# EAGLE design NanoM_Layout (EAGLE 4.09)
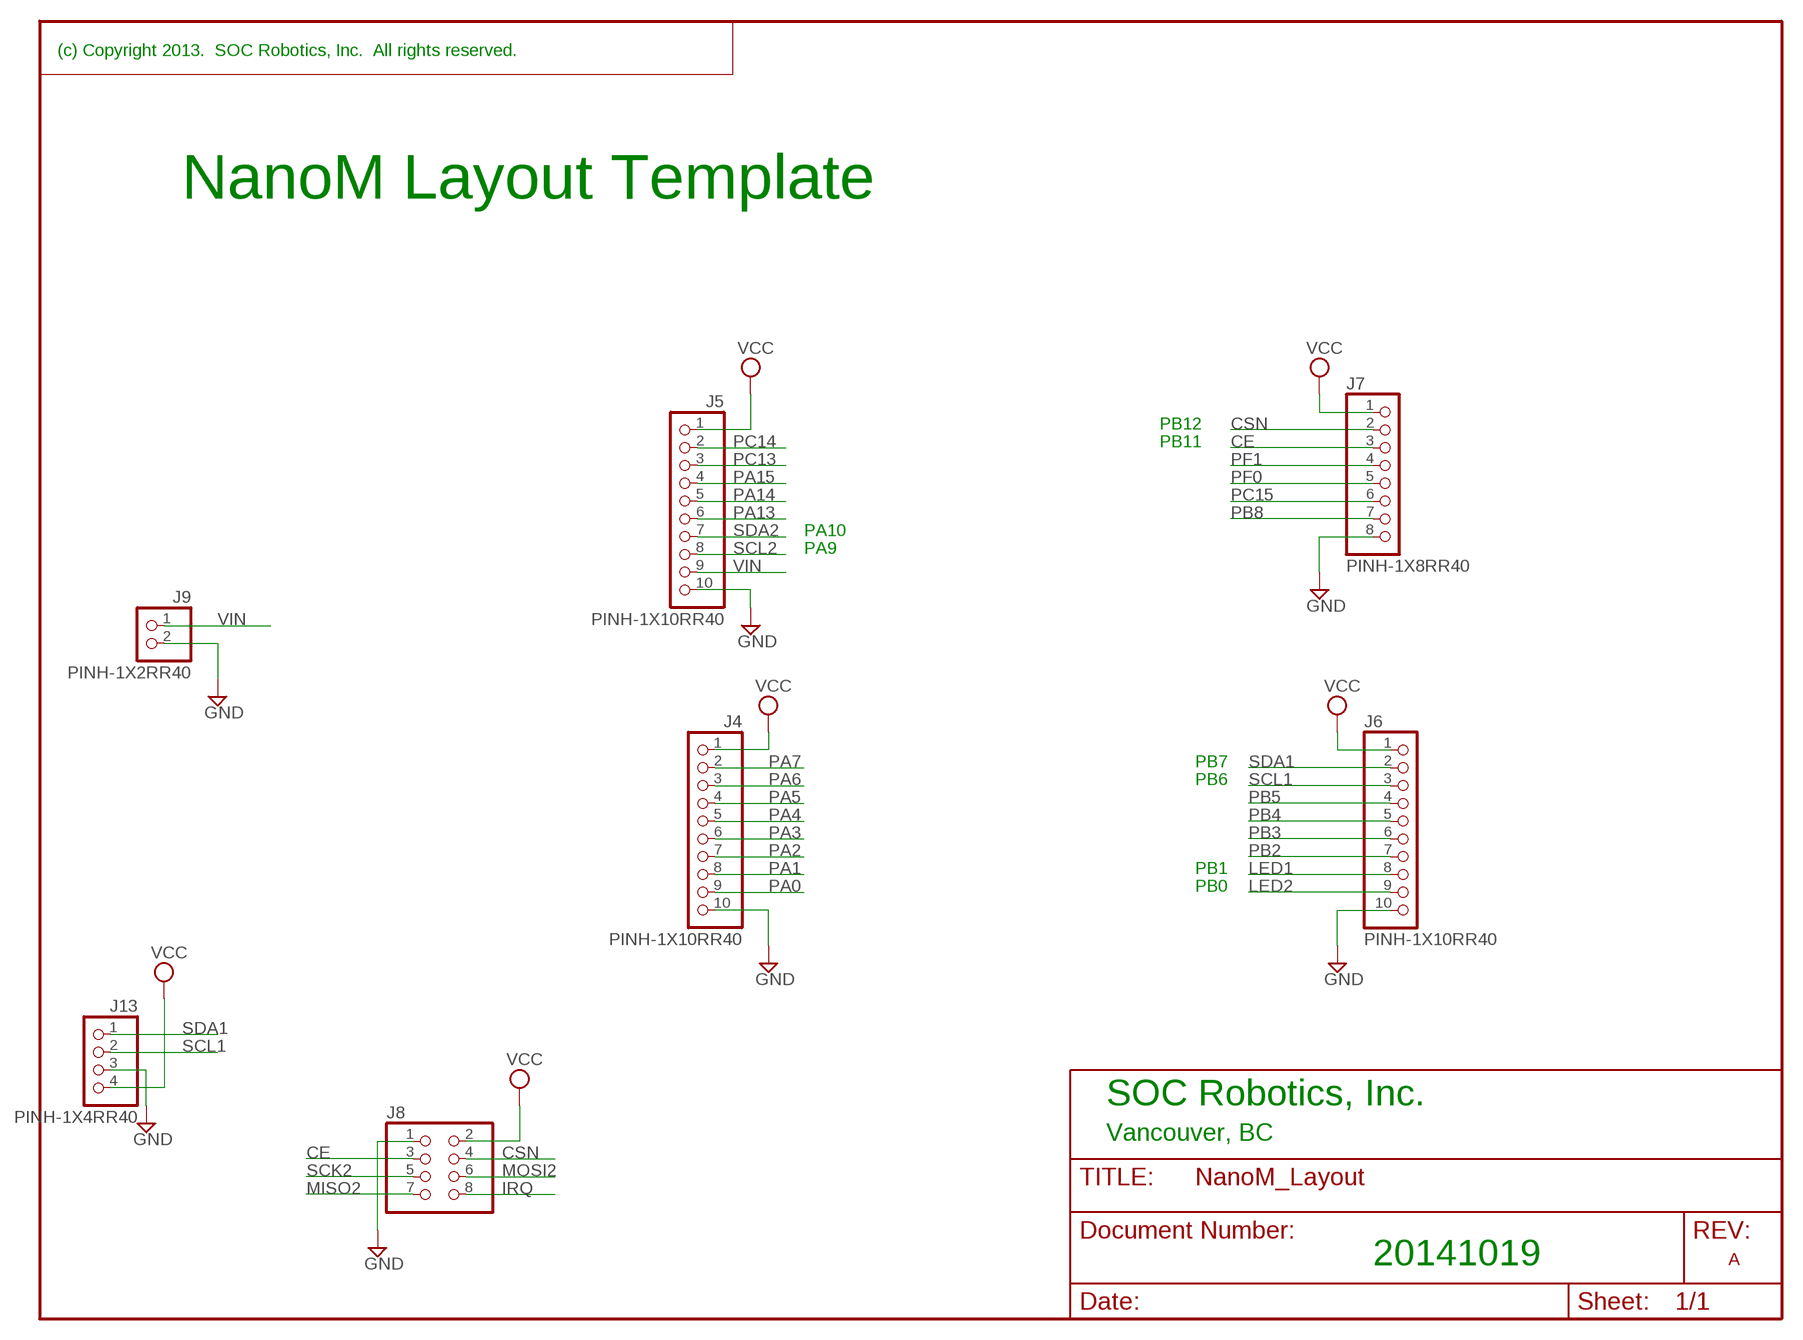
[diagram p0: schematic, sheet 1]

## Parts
J4  PINH-1X10RR40  [1X10ROUND]
J5  PINH-1X10RR40  [1X10ROUND]
J6  PINH-1X10RR40  [1X10ROUND]
J7  PINH-1X8RR40  [1X8ROUND]
J8  PINHD-2X4HEX  [2X04]
J9  PINH-1X2RR40  [1X2ROUND]
J13  PINH-1X4RR40  [1X4ROUND]

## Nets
CE: J7.3 J8.3
CSN: J7.2 J8.4
GND: J4.10 J5.10 J6.10 J7.8 J8.1 J9.2 J13.3
IRQ: J8.8
LED1: J6.8
LED2: J6.9
MISO2: J8.7
MOSI2: J8.6
PA0: J4.9
PA1: J4.8
PA2: J4.7
PA3: J4.6
PA4: J4.5
PA5: J4.4
PA6: J4.3
PA7: J4.2
PA13: J5.6
PA14: J5.5
PA15: J5.4
PB2: J6.7
PB3: J6.6
PB4: J6.5
PB5: J6.4
PB8: J7.7
PC13: J5.3
PC14: J5.2
PC15: J7.6
PF0: J7.5
PF1: J7.4
SCK2: J8.5
SCL1: J6.3 J13.2
SCL2: J5.8
SDA1: J6.2 J13.1
SDA2: J5.7
VCC: J4.1 J5.1 J6.1 J7.1 J8.2 J13.4
VIN: J5.9 J9.1

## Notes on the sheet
- (c) Copyright 2013.  SOC Robotics, Inc.  All rights reserved.
- NanoM Layout Template
- PB12
- PB11
- PA10
- PA9
- PB7
- PB6
- PB1
- PB0
- SOC Robotics, Inc.
- Vancouver, BC
- 20141019 | A

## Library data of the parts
J4-J6 = pinhead:PINH-1X10R
J7 = pinhead:PINH-1X8R
J8 = pinhead:PINHD-2X4: PIN HEADER
J9 = pinhead:PINH-1X2R: 1x2 Pin head round
J13 = pinhead:PINH-1X4R: 1x4 Pin Head Round

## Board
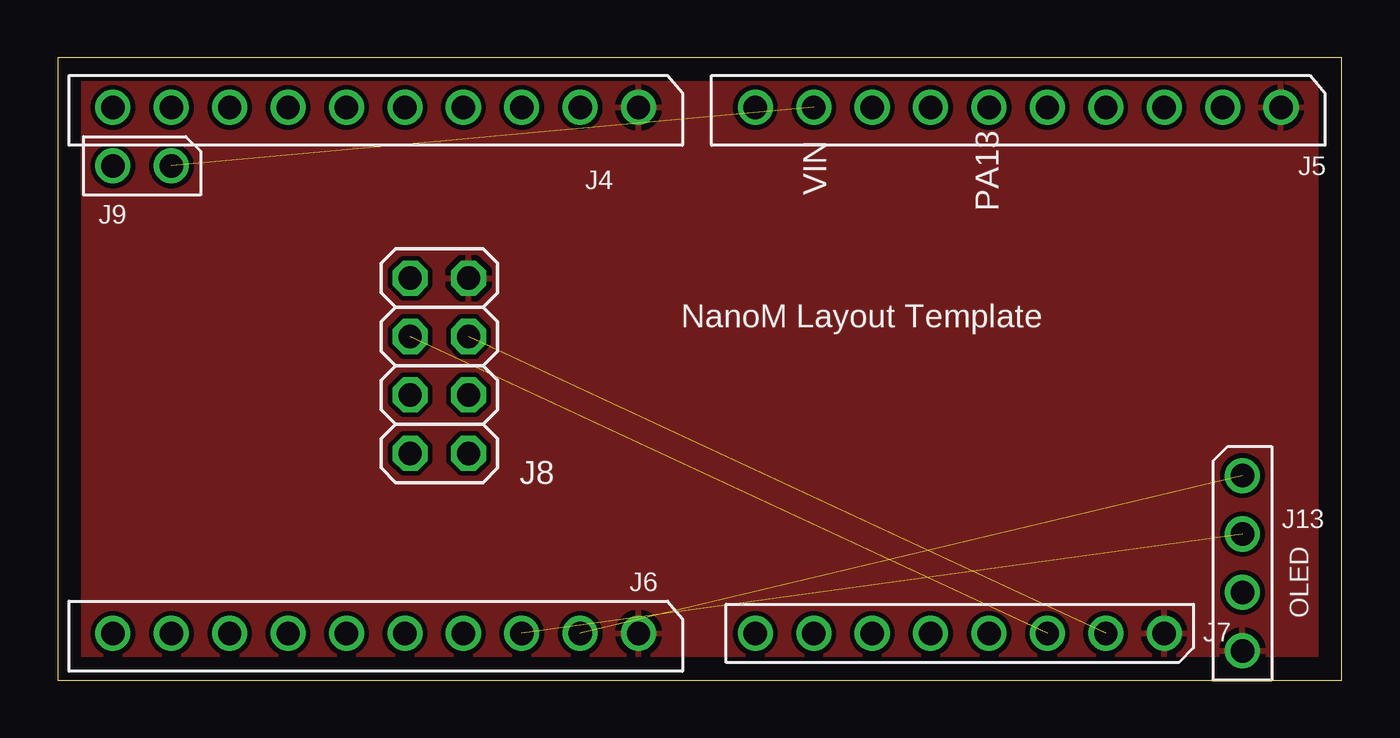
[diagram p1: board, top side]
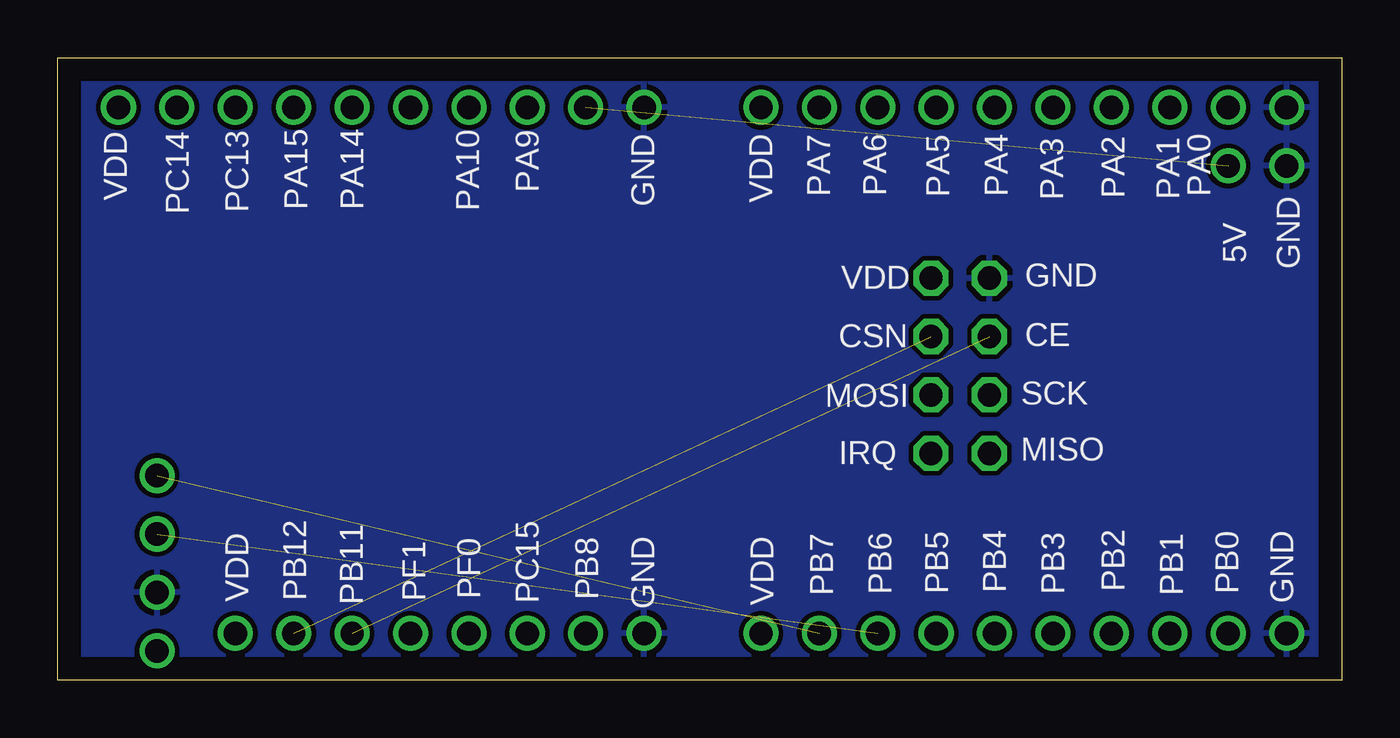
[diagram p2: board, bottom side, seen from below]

Size 55.86 x 27.08 mm. Coordinates in mm from the lower left corner, seen from the top.
Outline: 0,0 55.86,0 55.86,27.08 0,27.08 0,0
Copper layers used: Top, Bottom

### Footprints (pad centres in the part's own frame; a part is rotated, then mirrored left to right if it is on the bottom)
1X10ROUND = drill 1.016 round: 1 -11.43,0; 2 -8.89,0; 3 -6.35,0; 4 -3.81,0; 5 -1.27,0; 6 1.27,0; 7 3.81,0; 8 6.35,0; 9 8.89,0; 10 11.43,0
1X8ROUND = drill 1.016 round: 1 -8.89,0; 2 -6.35,0; 3 -3.81,0; 4 -1.27,0; 5 1.27,0; 6 3.81,0; 7 6.35,0; 8 8.89,0
2X04 = drill 1.016 octagon: 1 -3.81,-1.27; 2 -3.81,1.27; 3 -1.27,-1.27; 4 -1.27,1.27; 5 1.27,-1.27; 6 1.27,1.27; 7 3.81,-1.27; 8 3.81,1.27
1X2ROUND = drill 1.016 round: 1 -1.27,0; 2 1.27,0
1X4ROUND = drill 1.016 round: 1 -3.81,0; 2 -1.27,0; 3 1.27,0; 4 3.81,0

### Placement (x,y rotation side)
J4  13.84,24.9 180 top
J5  41.78,24.9 180 top
J6  13.84,2.04 180 top
J7  39.24,2.04 180 top
J8  16.61,13.68 270 top
J9  3.68,22.36 180 top
J13  51.53,5.09 270 top

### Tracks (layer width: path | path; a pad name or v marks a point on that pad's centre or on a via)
CE  (1 unrouted)
CSN  (1 unrouted)
GND
  pour Bottom: 0.12,26.96 55.75,26.96 55.75,0.11 0.12,0.11
SCL1  (1 unrouted)
SDA1  (1 unrouted)
VCC
  pour Top: 0.12,26.96 55.75,26.96 55.75,0.11 0.12,0.11
VIN  (1 unrouted)

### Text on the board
tPlace: VIN | PA13 | NanoM Layout Template | OLED
bPlace: PA0 | PA1 | PA2 | PA3 | PA4 | PA5 | PA6 | PA7 | VDD | GND | PA9 | PA10 | PA14 | PA15 | PC13 | PC14 | VDD | GND | 5V | GND | VDD | CE | CSN | SCK | MOSI | MISO | IRQ | GND | PB0 | PB2 | PB4 | PB5 | PC15 | PB11 | PB12 | PB1 | PB3 | PB6 | PB7 | VDD | GND | PB8 | PF0 | PF1 | VDD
